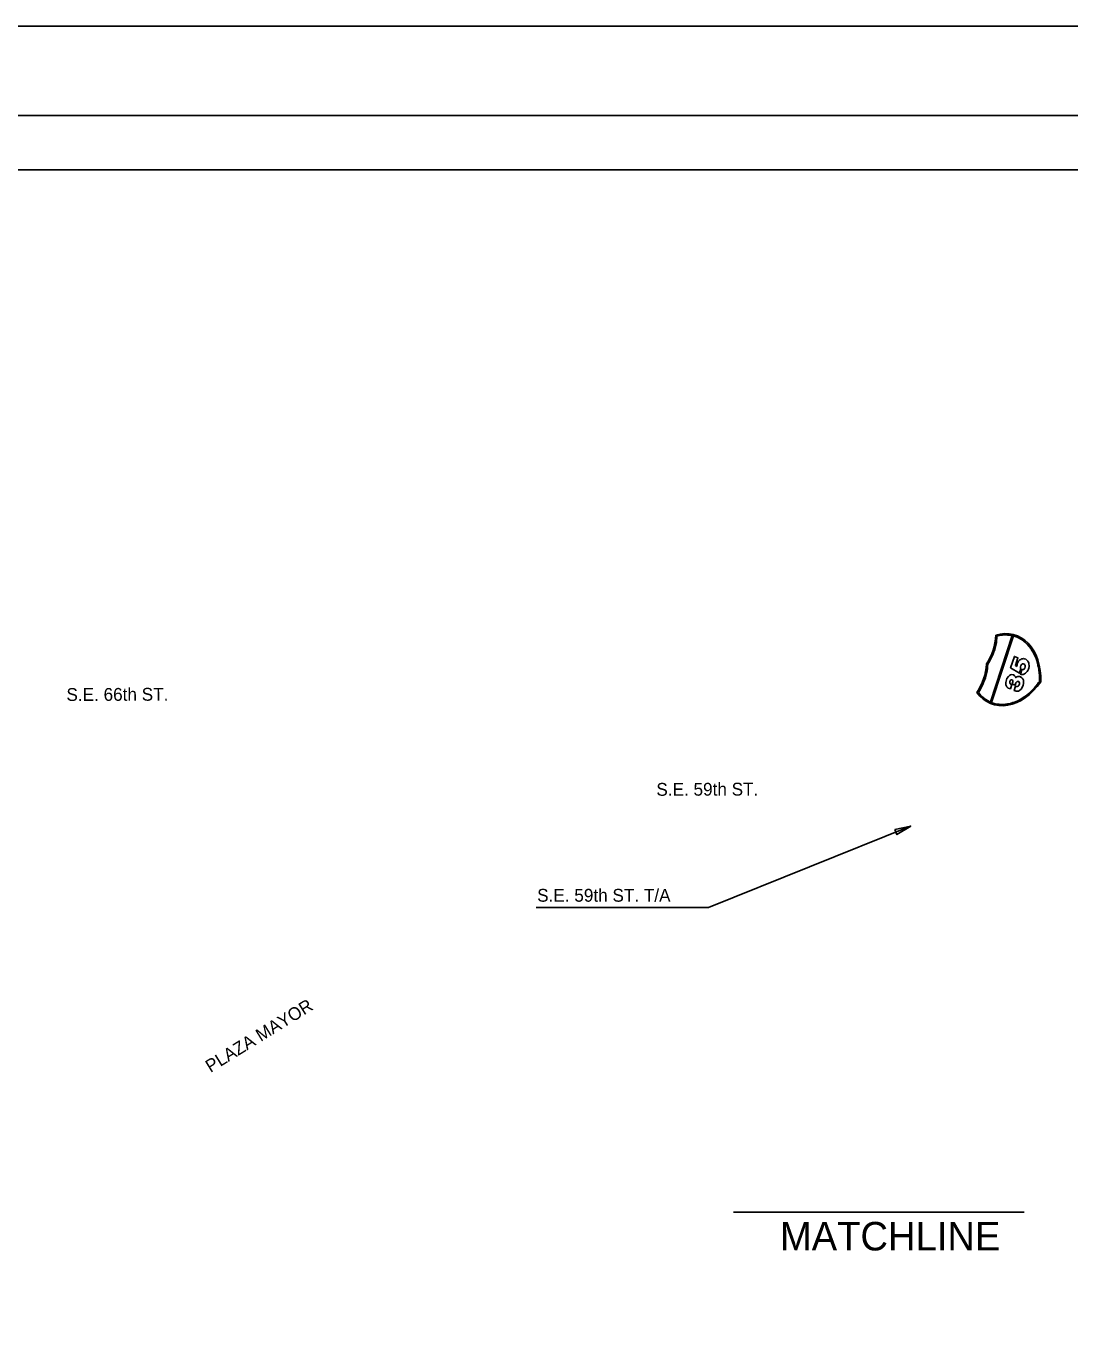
# Model space of a CAD drawing. Extents: x 2140911 to 2156666, y 139570 to 147689.
# Drawn here: x 2151304 to 2154561, y 143629 to 147689 of the extents above; entities that cross this region are included whole.
import ezdxf

# ---------------------------------------------------------------- set-up
doc = ezdxf.new("R2010")
doc.units = 0
for name, color, linetype in [('5', 7, 'Continuous'), ('7', 7, 'Continuous'), ('Default', 7, 'Continuous'), ('SHT_Match_Lines', 7, 'Continuous'), ('SHT_Plot_Shape_Full', 7, 'Continuous'), ('SHT_Plot_Shape_Half', 7, 'Continuous'), ('SHT_Sheet_Border', 7, 'Continuous'), ('ST-TEXT', 7, 'Continuous')]:
    doc.layers.add(name, color=color, linetype=linetype)

# ---------------------------------------------------------------- blocks, each defined once
blk = doc.blocks.new('ARROWHD')
at = {"layer": 'Default'}
blk.add_lwpolyline([(0.313, -0.054), (0.313, 0.052), (-0.005, -0.001)], close=True, dxfattribs=at)
blk = doc.blocks.new('i-35-shield')
at = {"layer": '7'}
blk.add_line((-18.46, 5.36), (18.44, 5.36), dxfattribs=at)
blk.add_line((-18.46, 5.36), (18.44, 5.36), dxfattribs=at)
for points in [[(-18.51, 4.66), (-18.53, 3.83), (-18.52, 3.24), (-18.48, 2.57), (-18.35, 1.51), (-18.16, 0.52), (-17.93, -0.38), (-17.62, -1.35), (-17.14, -2.55), (-16.62, -3.61), (-15.87, -4.91), (-15.07, -6.06), (-14.15, -7.22), (-13.32, -8.14), (-12.31, -9.13), (-11.77, -9.61), (-10.87, -10.36), (-9.96, -11.05), (-8.99, -11.73), (-7.81, -12.47), (-6.93, -12.98), (-5.68, -13.64), (-4.12, -14.37), (-3.06, -14.81), (-1.71, -15.32), (-0.77, -15.63), (-0.01, -15.87), (0.75, -15.63), (1.69, -15.32), (3.04, -14.81), (4.1, -14.37), (5.66, -13.64), (6.9, -12.98), (7.78, -12.47), (8.96, -11.73), (9.93, -11.05), (10.85, -10.36), (11.74, -9.61), (12.28, -9.13), (13.29, -8.14), (14.13, -7.22), (15.05, -6.06), (15.84, -4.91), (16.6, -3.61), (17.12, -2.55), (17.6, -1.35), (17.91, -0.38), (18.14, 0.52), (18.33, 1.51), (18.45, 2.57), (18.5, 3.24), (18.51, 3.83), (18.49, 4.66), (-18.51, 4.66)], [(-8.85, -4.7), (-6.35, -4.7), (-6.35, -5.22), (-6.27, -5.4), (-6.19, -5.55), (-5.93, -5.9), (-5.48, -6.12), (-5.31, -6.2), (-5.05, -6.27), (-4.61, -6.27), (-4.2, -6.2), (-3.69, -5.78), (-3.55, -5.47), (-3.55, -5.11), (-3.78, -4.71), (-3.93, -4.59), (-4.19, -4.44), (-4.63, -4.3), (-5.84, -4.3), (-5.84, -2.63), (-4.61, -2.63), (-4.28, -2.55), (-4.07, -2.43), (-3.8, -2.06), (-3.75, -1.98), (-3.75, -1.63), (-3.9, -1.39), (-4.06, -1.19), (-4.27, -1.07), (-4.61, -1), (-5.05, -1), (-5.51, -1.15), (-5.66, -1.22), (-6, -1.49), (-6.07, -1.61), (-6.24, -1.97), (-6.24, -2.47), (-8.54, -2.47), (-8.54, -1.24), (-8.42, -0.82), (-8.18, -0.41), (-7.93, -0.11), (-7.24, 0.46), (-6.77, 0.66), (-6.1, 0.84), (-5.44, 0.94), (-4.02, 0.94), (-2.69, 0.57), (-2, 0.19), (-1.74, -0.02), (-1.52, -0.32), (-1.15, -0.82), (-1.04, -1.52), (-1.04, -1.88), (-1.28, -2.47), (-1.4, -2.68), (-1.64, -2.99), (-2.01, -3.29), (-2.13, -3.35), (-1.79, -3.54), (-1.55, -3.76), (-1.18, -4.16), (-0.94, -4.75), (-0.83, -5.14), (-0.83, -5.58), (-1.06, -6.44), (-1.3, -6.85), (-1.54, -7.15), (-2, -7.54), (-2.35, -7.73), (-2.91, -8.02), (-3.7, -8.2), (-4.67, -8.3), (-5.55, -8.3), (-6.88, -8.02), (-7.68, -7.54), (-8.03, -7.25), (-8.37, -6.87), (-8.61, -6.56), (-8.85, -5.77), (-8.85, -4.7)], [(3.79, -2.06), (4.08, -1.94), (4.66, -1.84), (5.66, -1.84), (6.21, -1.93), (6.65, -2.03), (7.12, -2.22), (7.58, -2.51), (7.93, -2.79), (8.27, -3.18), (8.51, -3.57), (8.73, -4.03), (8.86, -4.45), (8.86, -5.42), (8.73, -5.84), (8.51, -6.3), (8.26, -6.71), (7.92, -6.99), (7.48, -7.45), (6.9, -7.74), (6.26, -8.01), (5.7, -8.2), (4.92, -8.3), (4.25, -8.3), (3.59, -8.2), (2.93, -8.02), (2.38, -7.83), (1.81, -7.55), (1.24, -7.07), (0.76, -6.47), (0.52, -5.68), (0.52, -5.05), (2.93, -5.05), (3.1, -5.49), (3.37, -5.94), (3.61, -6.14), (3.95, -6.29), (4.21, -6.35), (4.86, -6.35), (5.12, -6.28), (5.57, -6.13), (5.9, -5.85), (5.97, -5.74), (6.14, -5.39), (6.14, -4.82), (6.07, -4.64), (5.9, -4.36), (5.57, -4.09), (5.12, -3.94), (4.86, -3.86), (4.22, -3.86), (3.96, -3.93), (3.79, -4.01), (3.56, -4.13), (3.42, -4.39), (0.86, -4.39), (2.04, 0.85), (8.33, 0.85), (8.33, -1.17), (4, -1.17), (3.79, -2.06)]]:
    blk.add_lwpolyline(points, dxfattribs=at)
for points in [[(-18.51, 4.66), (-18.53, 3.83), (-18.52, 3.24), (-18.48, 2.57), (-18.35, 1.51), (-18.16, 0.52), (-17.93, -0.38), (-17.62, -1.35), (-17.14, -2.55), (-16.62, -3.61), (-15.87, -4.91), (-15.07, -6.06), (-14.15, -7.22), (-13.32, -8.14), (-12.31, -9.13), (-11.77, -9.61), (-10.87, -10.36), (-9.96, -11.05), (-8.99, -11.73), (-7.81, -12.47), (-6.93, -12.98), (-5.68, -13.64), (-4.12, -14.37), (-3.06, -14.81), (-1.71, -15.32), (-0.77, -15.63), (-0.01, -15.87), (0.75, -15.63), (1.69, -15.32), (3.04, -14.81), (4.1, -14.37), (5.66, -13.64), (6.9, -12.98), (7.78, -12.47), (8.96, -11.73), (9.93, -11.05), (10.85, -10.36), (11.74, -9.61), (12.28, -9.13), (13.29, -8.14), (14.13, -7.22), (15.05, -6.06), (15.84, -4.91), (16.6, -3.61), (17.12, -2.55), (17.6, -1.35), (17.91, -0.38), (18.14, 0.52), (18.33, 1.51), (18.45, 2.57), (18.5, 3.24), (18.51, 3.83), (18.49, 4.66)], [(-8.85, -5.77), (-8.61, -6.56), (-8.37, -6.87), (-8.03, -7.25), (-7.68, -7.54), (-6.88, -8.02), (-5.55, -8.3), (-4.67, -8.3), (-3.7, -8.2), (-2.91, -8.02), (-2.35, -7.73), (-2, -7.54), (-1.54, -7.15), (-1.3, -6.85), (-1.06, -6.44), (-0.83, -5.58), (-0.83, -5.14), (-0.94, -4.75), (-1.18, -4.16), (-1.55, -3.76), (-1.79, -3.54), (-2.13, -3.35), (-2.01, -3.29), (-1.64, -2.99), (-1.4, -2.68), (-1.28, -2.47), (-1.04, -1.88), (-1.04, -1.52), (-1.15, -0.82), (-1.52, -0.32), (-1.74, -0.02), (-2, 0.19), (-2.69, 0.57), (-4.02, 0.94), (-5.44, 0.94), (-6.1, 0.84), (-6.77, 0.66), (-7.24, 0.46), (-7.93, -0.11), (-8.18, -0.41), (-8.42, -0.82), (-8.54, -1.24), (-8.54, -2.47), (-6.24, -2.47), (-6.24, -1.97), (-6.07, -1.61), (-6, -1.49), (-5.66, -1.22), (-5.51, -1.15), (-5.05, -1), (-4.61, -1), (-4.27, -1.07), (-4.06, -1.19), (-3.9, -1.39), (-3.75, -1.63), (-3.75, -1.98), (-3.8, -2.06), (-4.07, -2.43), (-4.28, -2.55), (-4.61, -2.63), (-5.84, -2.63), (-5.84, -4.3), (-4.63, -4.3), (-4.19, -4.44), (-3.93, -4.59), (-3.78, -4.71), (-3.55, -5.11), (-3.55, -5.47), (-3.69, -5.78), (-4.2, -6.2), (-4.61, -6.27), (-5.05, -6.27), (-5.31, -6.2), (-5.48, -6.12), (-5.93, -5.9), (-6.19, -5.55), (-6.27, -5.4), (-6.35, -5.22), (-6.35, -4.7), (-8.85, -4.7)], [(3.79, -2.06), (4.08, -1.94), (4.66, -1.84), (5.66, -1.84), (6.21, -1.93), (6.65, -2.03), (7.12, -2.22), (7.58, -2.51), (7.93, -2.79), (8.27, -3.18), (8.51, -3.57), (8.73, -4.03), (8.86, -4.45), (8.86, -5.42), (8.73, -5.84), (8.51, -6.3), (8.26, -6.71), (7.92, -6.99), (7.48, -7.45), (6.9, -7.74), (6.26, -8.01), (5.7, -8.2), (4.92, -8.3), (4.25, -8.3), (3.59, -8.2), (2.93, -8.02), (2.38, -7.83), (1.81, -7.55), (1.24, -7.07), (0.76, -6.47), (0.52, -5.68), (0.52, -5.05), (2.93, -5.05), (3.1, -5.49), (3.37, -5.94), (3.61, -6.14), (3.95, -6.29), (4.21, -6.35), (4.86, -6.35), (5.12, -6.28), (5.57, -6.13), (5.9, -5.85), (5.97, -5.74), (6.14, -5.39), (6.14, -4.82), (6.07, -4.64), (5.9, -4.36), (5.57, -4.09), (5.12, -3.94), (4.86, -3.86), (4.22, -3.86), (3.96, -3.93), (3.79, -4.01), (3.56, -4.13), (3.42, -4.39), (0.86, -4.39), (2.04, 0.85), (8.33, 0.85), (8.33, -1.17), (4, -1.17)]]:
    blk.add_lwpolyline(points, close=True, dxfattribs=at)
for centre, major_axis, start_param, end_param in [((11.77, 3.87), (31.01, 0), 2.678593, 4.322471), ((-7.87, 27.69), (-21.16, 0), 1.177968, 1.951302), ((-11.8, 3.87), (-31.01, 0), 1.960714, 3.604592), ((7.85, 27.69), (21.16, 0), 4.331883, 5.105218)]:
    blk.add_ellipse(centre, major_axis=major_axis, ratio=0.713476, start_param=start_param, end_param=end_param, dxfattribs=at)
for points in [[(-15.68, 12.94), (-16.64, 11.49), (-17.36, 9.97), (-18.15, 7.41), (-18.36, 6.39), (-18.46, 5.36)], [(-15.68, 12.94), (-16.64, 11.49), (-17.36, 9.97), (-18.15, 7.41), (-18.36, 6.39), (-18.46, 5.36)], [(-15.68, 12.94), (-14.13, 12.51), (-12.51, 12.21), (-7.22, 11.69), (-3.45, 12), (-0.01, 12.95)], [(-0.01, 12.95), (-3.45, 12), (-7.22, 11.69), (-12.51, 12.21), (-14.13, 12.51), (-15.68, 12.94)], [(-0.01, 12.95), (1.63, 12.5), (3.36, 12.18), (8.65, 11.7), (12.31, 12.02), (15.65, 12.94)], [(15.65, 12.94), (12.31, 12.02), (8.65, 11.7), (3.36, 12.18), (1.63, 12.5), (-0.01, 12.95)], [(18.44, 5.36), (18.35, 6.27), (18.18, 7.17), (17.45, 9.74), (16.68, 11.38), (15.65, 12.94)], [(18.44, 5.36), (18.35, 6.27), (18.18, 7.17), (17.45, 9.74), (16.68, 11.38), (15.65, 12.94)]]:
    blk.add_open_spline(points, degree=3, dxfattribs=at)

msp = doc.modelspace()

# ---------------------------------------------------------------- linework, layer by layer
at = {"layer": '5'}
for p in [(2154064.1, 145192.1), (2152895.9, 144938.3)]:
    msp.add_line(p, (2153433.5, 144938.3), dxfattribs=at)
at = {"layer": '7'}
msp.add_lwpolyline([(2154313, 145579.7), (2154316.8, 145578.1), (2154385.2, 145785.6), (2154381.1, 145786.6)], close=True, dxfattribs=at)
at = {"layer": 'SHT_Match_Lines'}
msp.add_line((2153511.8, 143987.4), (2154417.9, 143987.4), dxfattribs=at)
at = {"layer": 'SHT_Plot_Shape_Full'}
msp.add_lwpolyline([(2144487.6, 147688.9), (2156666.2, 147688.9), (2156666.2, 139569.8), (2144487.6, 139569.8)], close=True, dxfattribs=at)
at = {"layer": 'SHT_Plot_Shape_Half'}
msp.add_lwpolyline([(2145041.5, 147409.9), (2156543.6, 147409.9), (2156543.6, 139967.3), (2145041.5, 139967.3)], close=True, dxfattribs=at)
at = {"layer": 'SHT_Sheet_Border'}
msp.add_lwpolyline([(2156357.5, 140136.5), (2145701.2, 140136.5), (2145701.2, 147240.7), (2156357.5, 147240.7)], close=True, dxfattribs=at)

# ---------------------------------------------------------------- block references
at = {"layer": '5', "xscale": 157.48000000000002, "yscale": 157.47999999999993, "rotation": -158.08307391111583}
msp.add_blockref('ARROWHD', (2154064.1, 145192.1), dxfattribs=at)
at = {"layer": '7', "xscale": 5.905500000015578, "yscale": 5.905500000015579, "rotation": 71.78521686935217}
msp.add_blockref('i-35-shield', (2154377.2, 145673.3), dxfattribs=at)

# ---------------------------------------------------------------- texts
at = {"layer": 'SHT_Match_Lines'}
msp.add_text('MATCHLINE', height=89.02, dxfattribs=at).set_placement((2153656.3, 143868.2))
at = {"layer": 'ST-TEXT'}
for s, rotation, p in [('S.E. 66th ST.', 0.1579, (2151430.3, 145582.9)), ('S.E. 59th ST.', 0.1579, (2153270.9, 145286.9)), ('PLAZA MAYOR', 31.6564, (2151879.7, 144421.8))]:
    msp.add_text(s, height=40, rotation=rotation, dxfattribs=at).set_placement(p)
msp.add_text('S.E. 59th ST. T/A', height=40, dxfattribs=at).set_placement((2152898.9, 144956.4))

doc.saveas('drawing.dxf')
